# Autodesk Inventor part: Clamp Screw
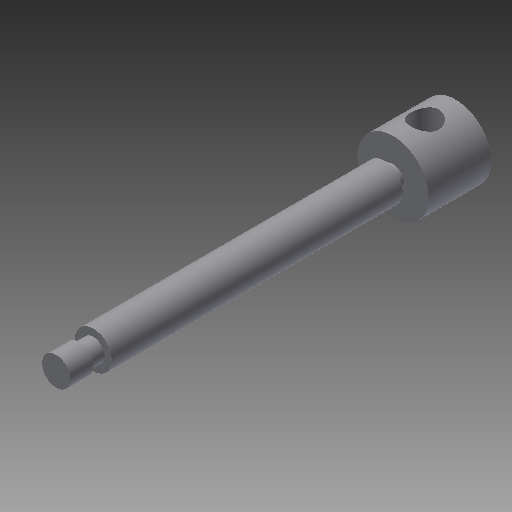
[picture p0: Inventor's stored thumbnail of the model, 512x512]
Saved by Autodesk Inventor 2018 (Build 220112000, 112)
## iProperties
Shininess: 77.0
Length Units: 11269
Angle Units: 11279
Time Units: 11290
Mass Units: 11283
Length Display Precision: 3
Angle Display Precision: 2
Created: 2002-02
Part Number: Clamp Screw
Document SubType Name: Modeling
Designer: ***
Density: 1 g/cm^3
Material: Generic
Appearance: Default
Density: 0.0
Volumn: 0.0
Area: 0.0
PropertySet Name: Model Information
Control State: 0
Master: False
Checked Out: False
Author: ***
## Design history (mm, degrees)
sketch "Sketch1"
  geometry: L1 (0, 140)-(5, 140); L2 (5, 140)-(5, 132); L3 (5, 132)-(4, 132); L4 (4, 132)-(4, 127); L5 (4, 127)-(6.5, 127); L6 (6.5, 127)-(6.5, 25); L7 (6.5, 25)-(4, 25); L8 (4, 25)-(4, 22); L9 (4, 22)-(12.5, 22); L10 (12.5, 22)-(12.5, 0); L11 (12.5, 0)-(0, 0); L12 (0, 0)-(0, 140)
  constraints: 24 end point, 10 parallel, 1 horizontal, 1 perpendicular
  dimensions: "d0" = 10 diameter of L2 L12; "d1" = 8 diameter of L4 L12; "d2" = 13 diameter of L6 L12; "d3" = 8 diameter of L7.end L12; "d4" = 25 diameter of L10 L12; "d5" = 3 distance from line of L7.end L9; "d6" = 8 distance of L1.end L2.end; "d7" = 13 vertical distance of L1.end L5.end; "d8" = 22 distance of L9.end L10.end; "d10" = 102 distance of L5.end L6.end
revolve "Revolution1" sketch "Sketch1" stored, may be unused: angle "d11" = 90 deg
sketch "Sketch3"
  geometry: L1 (-12.5, 0)-(12.5, 0) reference; C1 r 5 at (-0.113, 11)
  constraints: 1 centre point
  dimensions: "d13" = 10 diameter of C1; "d14" = 11 distance from line of L1 C1.centre
extrude "Extrusion1" cut sketch "Sketch3" extent not by distance; stored distance "d15" = 10; taper "d16" = 0 deg
body "Solid1"
